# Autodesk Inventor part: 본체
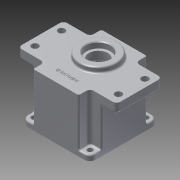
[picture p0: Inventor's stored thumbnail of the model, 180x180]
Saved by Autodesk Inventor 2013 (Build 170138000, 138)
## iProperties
Created: 2015-07
Part Number: 본체
Material: 알루미늄 6061
Document SubType Name: 판금
Designer: user
Density: 2.71 g/cm^3
Sheet Metal Rule: 기본값
Author: user
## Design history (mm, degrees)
sketch "스케치1"
  geometry: L1 (-45, 45)-(45, 45); L2 (45, 45)-(45, -45); L3 (45, -45)-(-45, -45); L4 (-45, -45)-(-45, 45); L5 (-45, 45)-(45, -45); L6 (45, 45)-(-45, -45); 1 further point
  constraints: 12 end point, 2 midpoint, 2 parallel, 1 horizontal, 1 perpendicular
  dimensions: "d0" = 90 distance of L2.end L3.end; "d1" = 90 distance of L1.end L2.end
extrude "돌출1" new body sketch "스케치1" distance "d2" = 70; taper "d3" = 0 deg
sketch "스케치2"
  geometry: L1 (45, -45)-(45, 45) reference; L2 (0, 0)-(0, 11); C1 r 25 at (0, 11)
  constraints: 2 end point, 1 centre point, 1 coincident, 1 parallel
  dimensions: "d4" = 11 distance of L2.start L2.end; "d5" = 50 diameter of C1
extrude "돌출2" join sketch "스케치2" distance "d6" = 7; taper "d7" = 0 deg
sketch "스케치3"
  geometry: C1 r 40 at (0, 0); 1 further point
  constraints: 1 centre point, 1 coincident
  dimensions: "d8" = 80 diameter of C1
extrude "돌출3" cut sketch "스케치3" distance "d9" = 9; taper "d10" = 0 deg
sketch "스케치4"
  geometry: L1 (65, -30)-(-65, -30); L2 (-65, -30)-(-65, 30); L3 (-65, 30)-(65, 30); L4 (65, 30)-(65, -30); L5 (65, -30)-(-65, 30); L6 (-65, -30)-(65, 30); 1 further point
  constraints: 12 end point, 2 midpoint, 2 parallel, 1 horizontal, 1 perpendicular
  dimensions: "d11" = 130 distance of L2.end L3.end; "d12" = 60 distance of L1.end L2.end
extrude "돌출4" join sketch "스케치4" distance "d13" = 12; taper "d14" = 0 deg
sketch "스케치5"
  geometry: L1 (-45, 45)-(-30, 45); L2 (-30, 45)-(-30, 30); L3 (-30, 30)-(-45, 30); L4 (-45, 30)-(-45, 45); 1 further point
  constraints: 8 end point, 2 parallel, 1 horizontal, 1 perpendicular
  dimensions: "d15" = 15 distance of L2.end L3.end; "d16" = 15 distance of L1.end L2.end
extrude "돌출5" cut sketch "스케치5" distance "d17" = 63; taper "d18" = 0 deg
fillet "모깎기1" dims "d22" = 5
fillet "모깎기2" dims "d23" = 8
sketch "스케치6"
  geometry: C1 r 40 at (0, 0) reference; C2 r 39 at (0, 0)
  constraints: 1 centre point, 1 coincident
  dimensions: "d24" = 78 diameter of C2
extrude "돌출6" cut sketch "스케치6" distance "d25" = 52; taper "d26" = 0 deg
fillet "모깎기3" dims "d27" = 2
fillet "모깎기4" dims "d28" = 2
sketch "스케치7"
  geometry: L1 (0, 0)-(0, 11); L2 (0, 0)-(0, -20); C1 r 39 at (0, 0) reference; A1 r 20.5 centre (0, 11) between (7.402, -8.117) and (-7.402, -8.117); A2 r 14 centre (0, -20) between (-7.402, -8.117) and (7.402, -8.117)
  constraints: 4 end point, 4 point on circle, 2 centre point, 2 coincident, 1 collinear, 1 vertical
  dimensions: "d29" = 11 distance of L1.start L1.end; "d30" = 41 diameter of A1; "d31" = 20 distance of L1.start L2.end; "d32" = 28 diameter of A2
extrude "돌출7" join sketch "스케치7" distance "d33" = 7; taper "d34" = 0 deg
fillet "모깎기5" dims "d35" = 3
sketch "스케치8"
  geometry: C1 r 17.5 at (0, 11); A1 r 18.5 centre (0, 11) between (10.031, -4.545) and (-10.031, -4.545) reference; 1 further point
  constraints: 1 centre point, 1 coincident
  dimensions: "d37" = 35 diameter of C1
extrude "돌출8" cut sketch "스케치8" distance "d38" = 10; taper "d39" = 0 deg
sketch "스케치9"
  geometry: C1 r 17.5 at (0, 0) reference; C2 r 12.5 at (0, 0); 1 further point
  constraints: 1 centre point, 1 coincident
  dimensions: "d40" = 25 diameter of C2
extrude "돌출9" cut sketch "스케치9" distance "d41" = 5; taper "d42" = 0 deg
sketch "스케치12"
  geometry: C1 r 25 at (0, 0) reference; C2 r 16 at (0, 0); 1 further point
  constraints: 1 centre point, 1 coincident
  dimensions: "d46" = 32 diameter of C2
extrude "돌출11" cut sketch "스케치12" distance "d47" = 8; taper "d48" = 0 deg
sketch "스케치13"
  geometry: C1 r 11 at (0, -20); A1 r 12 centre (0, -20) between (-8.994, -12.056) and (8.994, -12.056) reference; 1 further point
  constraints: 1 centre point, 1 coincident
  dimensions: "d49" = 22 diameter of C1
extrude "돌출12" cut sketch "스케치13" distance "d50" = 7; taper "d51" = 0 deg
sketch "스케치14"
  geometry: C1 r 11 at (0, 0) reference; C2 r 9.5 at (0, 0); 1 further point
  constraints: 1 centre point, 1 coincident
  dimensions: "d52" = 19 diameter of C2
extrude "돌출13" cut sketch "스케치14" distance "d53" = 1; taper "d54" = 0 deg
fillet "모깎기7" dims "d55" = 2
fillet "모깎기8" dims "d56" = 0.3
chamfer "모따기1" distance "d57" = 1; stored, may be unused: second distance "d58" = 2, angle "d59" = 45 deg
fillet "모깎기9" dims "d60" = 2
sketch "스케치15"
  geometry: L1 (-24.749, -24.749)-(24.749, 24.749); A1 r 4 centre (-24.749, 24.749) between (-27.462, 21.809) and (-21.809, 27.462); A2 r 4 centre (24.749, 24.749) between (21.809, 27.462) and (27.462, 21.809); A3 r 4 centre (24.749, -24.749) between (27.462, -21.809) and (21.809, -27.462); A4 r 4 centre (-24.749, -24.749) between (-21.809, -27.462) and (-27.462, -21.809); A5 r 3.5 centre (-19.238, 29.836) between (-21.134, 32.777) and (-21.762, 27.412); A6 r 3.5 centre (-29.836, 19.238) between (-27.412, 21.762) and (-32.777, 21.134); A7 r 3.5 centre (19.238, 29.836) between (21.762, 27.412) and (21.134, 32.777); A8 r 3.5 centre (29.836, 19.238) between (32.777, 21.134) and (27.412, 21.762); A9 r 3.5 centre (-19.238, -29.836) between (-21.762, -27.412) and (-21.134, -32.777); A10 r 3.5 centre (-29.836, -19.238) between (-32.777, -21.134) and (-27.412, -21.762); A11 r 3.5 centre (19.238, -29.836) between (21.134, -32.777) and (21.762, -27.412); A12 r 3.5 centre (29.836, -19.238) between (27.412, -21.762) and (32.777, -21.134); A13 r 39 centre (0, 0) between (21.134, -32.777) and (32.777, -21.134); A14 r 39 centre (0, 0) between (-32.777, -21.134) and (-21.134, -32.777); A15 r 39 centre (0, 0) between (32.777, 21.134) and (21.134, 32.777); A16 r 39 centre (0, 0) between (-21.134, 32.777) and (-32.777, 21.134)
  constraints: 40 point on circle, 16 centre point, 2 coincident, 2 end point, 1 midpoint, 1 tangent
  dimensions: "d63" = 8 diameter of A1; "d64" = 8 diameter of A2; "d66" = 8 diameter of A4; "d67" = 7 diameter of A5; "d68" = 4 radius of A3
extrude "돌출14" join sketch "스케치15" distance "d69" = 52; taper "d70" = 0 deg
fillet "모깎기10" dims "d71" = 2
sketch "스케치16"
  geometry: C1 r 2 at (-24.749, 24.749); A1 r 4 centre (-24.749, 24.749) between (-27.462, 21.809) and (-21.809, 27.462) reference
  constraints: 1 centre point, 1 coincident
  dimensions: "d72" = 4 diameter of C1
hole "구멍1" sketch "스케치16" at (-24.749, 24.749) diameter "d73" = 3.459; stored, may be unused: countersink angle "d77" = 90 deg, drill point angle "d79" = 118 deg; dims "d74" = 12, "d75" = 4, "d76" = 2, "d78" = 15
sketch "스케치17"
  geometry: L1 (55, -17.5)-(-55, -17.5); L2 (-55, -17.5)-(-55, 17.5); L3 (-55, 17.5)-(55, 17.5); L4 (55, 17.5)-(55, -17.5); L5 (55, -17.5)-(-55, 17.5); L6 (-55, -17.5)-(55, 17.5); C1 r 4.5 at (-55, 17.5); C2 r 4.5 at (-55, -17.5); C3 r 4.5 at (55, -17.5); C4 r 4.5 at (55, 17.5); 1 further point
  constraints: 12 end point, 4 centre point, 4 coincident, 2 midpoint, 2 parallel, 1 horizontal, 1 perpendicular
  dimensions: "d83" = 110 distance of L2.end L3.end; "d84" = 35 distance of L1.end L2.end; "d85" = 9 diameter of C1; "d86" = 9 diameter of C2; "d87" = 9 diameter of C3; "d88" = 9 diameter of C4
extrude "돌출15" cut sketch "스케치17" distance "d89" = 52; taper "d90" = 0 deg
sketch "스케치18"
  geometry: C1 r 3.5 at (-37, 37); C2 r 3.5 at (37, 37); C3 r 3.5 at (37, -37); C4 r 3.5 at (-37, -37); A1 r 8 centre (37, -37) between (37, -45) and (45, -37) reference; A2 r 8 centre (37, 37) between (45, 37) and (37, 45) reference; A3 r 8 centre (-37, 37) between (-37, 45) and (-45, 37) reference; A4 r 8 centre (-37, -37) between (-45, -37) and (-37, -45) reference
  constraints: 4 centre point, 4 coincident
  dimensions: "d91" = 7 diameter of C1; "d92" = 7 diameter of C2; "d93" = 7 diameter of C3; "d94" = 7 diameter of C4
extrude "돌출16" cut sketch "스케치18" distance "d95" = 52; taper "d96" = 0 deg
sketch "스케치19"
  geometry: L1 (-28, -45)-(28, -45) reference; L2 (-15, -25)-(15, -25); L3 (15, -25)-(15, -35); L4 (15, -35)-(-15, -35); L5 (-15, -35)-(-15, -25); C1 r 27 at (0, 11) reference; 1 further point
  constraints: 2 other
  dimensions: "d97" = 10 distance of L2.end L3.end; "d99" = 10 distance between parallel lines of L1 L4; "d100" = 30 distance of L3.end L4.end; "d101" = 15 distance from line of L3 C1.centre
feature "엠보싱1" sketch "스케치19" dims "d102" = 0.5, "d103" = 0
fillet "모깎기11" dims "d104" = 2
node "솔리드1"
pattern_circular "원형 패턴1" dims angle "d20" = 360 deg
pattern_circular "원형 패턴2" dims angle "d81" = 360 deg
other parameters: "K계수" = 4.4, "BendRadius" = 3.048 (derived), "BendReliefWidth" = 3.048 (derived), "BendReliefDepth" = 1.524 (derived), "CornerReliefSize" = 12.192 (derived), "SeamGap" = 0.01, "MinimumRemnant" = 6.096 (derived), "TransitionRadius" = 3.048 (= BendRadius)
